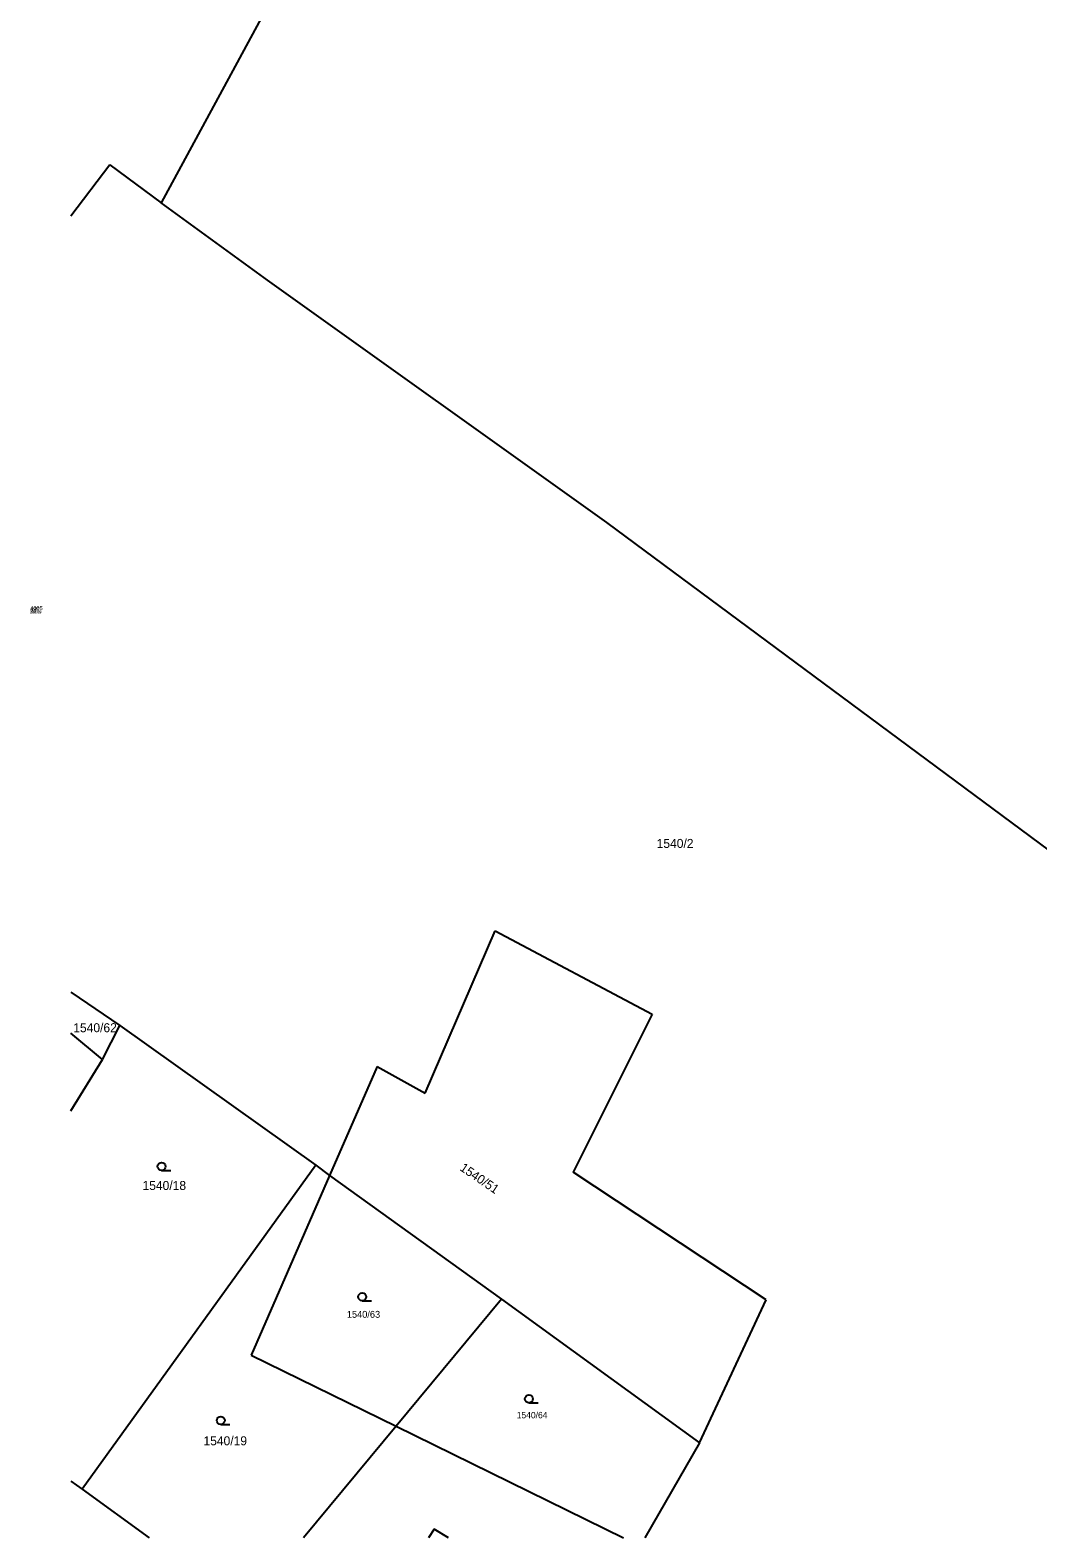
# Model space of a CAD drawing. Extents: x -805057 to -804930, y -994399 to -994240.
# Drawn here: x -805057 to -805019, y -994399.5 to -994342.6 of the extents above; entities that cross this region are included whole.
import ezdxf

# ---------------------------------------------------------------- set-up
doc = ezdxf.new("R2010")
doc.units = 0
for name, color, linetype in [('bod cislo', 7, 'Continuous'), ('bod pozice', 7, 'Continuous'), ('bod výška', 7, 'Continuous'), ('Katastralni mapa', 7, 'Continuous')]:
    doc.layers.add(name, color=color, linetype=linetype)

msp = doc.modelspace()

# ---------------------------------------------------------------- linework, layer by layer
at = {"layer": 'bod pozice'}
for p, q in [((-805057, -994364.5), (-805057, -994364.5)), ((-805056.99, -994364.47), (-805056.99, -994364.47))]:
    msp.add_line(p, q, dxfattribs=at)
at = {"layer": 'Katastralni mapa'}
for points in [[(-805038.84, -994324.69), (-805052.05, -994349.11)], [(-805053.99, -994347.68), (-805055.46, -994349.608)], [(-805053.99, -994347.68), (-805052.05, -994349.11)], [(-805048.04, -994352.03), (-805052.05, -994349.11)], [(-805035.24, -994361.16), (-805048.04, -994352.03)], [(-805012.5, -994378.01), (-805035.24, -994361.16)], [(-805042.09, -994382.69), (-805039.45, -994376.57)], [(-805039.45, -994376.57), (-805033.53, -994379.71)], [(-805055.46, -994378.881), (-805053.62, -994380.14)], [(-805054.27, -994381.42), (-805053.62, -994380.14)], [(-805053.62, -994380.14), (-805046.22, -994385.41)], [(-805033.53, -994379.71), (-805036.51, -994385.67)], [(-805054.27, -994381.42), (-805055.46, -994380.425)], [(-805055.46, -994383.357), (-805054.27, -994381.42)], [(-805043.9, -994381.68), (-805045.7, -994385.79)], [(-805043.9, -994381.68), (-805042.09, -994382.69)], [(-805046.22, -994385.41), (-805055.04, -994397.63)], [(-805052.04, -994385.6), (-805051.689, -994385.6)], [(-805045.7, -994385.79), (-805048.66, -994392.57)], [(-805046.22, -994385.41), (-805045.7, -994385.79)], [(-805045.7, -994385.79), (-805039.21, -994390.46)], [(-805029.23, -994390.48), (-805036.51, -994385.67)], [(-805044.47, -994390.52), (-805044.119, -994390.52)], [(-805039.21, -994390.46), (-805043.19, -994395.25)], [(-805039.21, -994390.46), (-805031.74, -994395.88)], [(-805031.74, -994395.88), (-805029.23, -994390.48)], [(-805048.66, -994392.57), (-805043.19, -994395.25)], [(-805038.181, -994394.371), (-805037.829, -994394.371)], [(-805049.81, -994395.18), (-805049.459, -994395.18)], [(-805043.19, -994395.25), (-805046.691, -994399.46)], [(-805043.19, -994395.25), (-805034.612, -994399.46)], [(-805031.74, -994395.88), (-805033.801, -994399.46)], [(-805055.46, -994397.325), (-805055.04, -994397.63)], [(-805055.04, -994397.63), (-805052.515, -994399.46)], [(-805041.76, -994399.13), (-805041.964, -994399.46)], [(-805041.212, -994399.46), (-805041.76, -994399.13)]]:
    msp.add_lwpolyline(points, dxfattribs=at)
for centre in [(-805052.04, -994385.45), (-805044.47, -994390.37), (-805038.18, -994394.22), (-805049.81, -994395.03)]:
    msp.add_circle(centre, 0.151, dxfattribs=at)

# ---------------------------------------------------------------- texts
at = {"layer": 'bod cislo'}
for s, p in [('490    ', (-805057, -994364.5)), ('4005    ', (-805056.99, -994364.47))]:
    msp.add_text(s, height=0.15, dxfattribs=at).set_placement(p)
at = {"layer": 'bod výška'}
for p in [(-805057, -994364.6), (-805056.99, -994364.57)]:
    msp.add_text('288.65  ', height=0.1, dxfattribs=at).set_placement(p)
at = {"layer": 'Katastralni mapa'}
for s, height, p in [('1540/2', 0.34, (-805033.36, -994373.44)), ('1540/62', 0.34, (-805055.373, -994380.39)), ('1540/18', 0.34, (-805052.76, -994386.34)), ('1540/63', 0.26, (-805045.05, -994391.16)), ('1540/64', 0.24, (-805038.64, -994394.95)), ('1540/19', 0.34, (-805050.46, -994395.97))]:
    msp.add_text(s, height=height, dxfattribs=at).set_placement(p)
msp.add_text('1540/51', height=0.34, rotation=325.8026, dxfattribs=at).set_placement((-805040.815, -994385.578))

doc.saveas('drawing.dxf')
